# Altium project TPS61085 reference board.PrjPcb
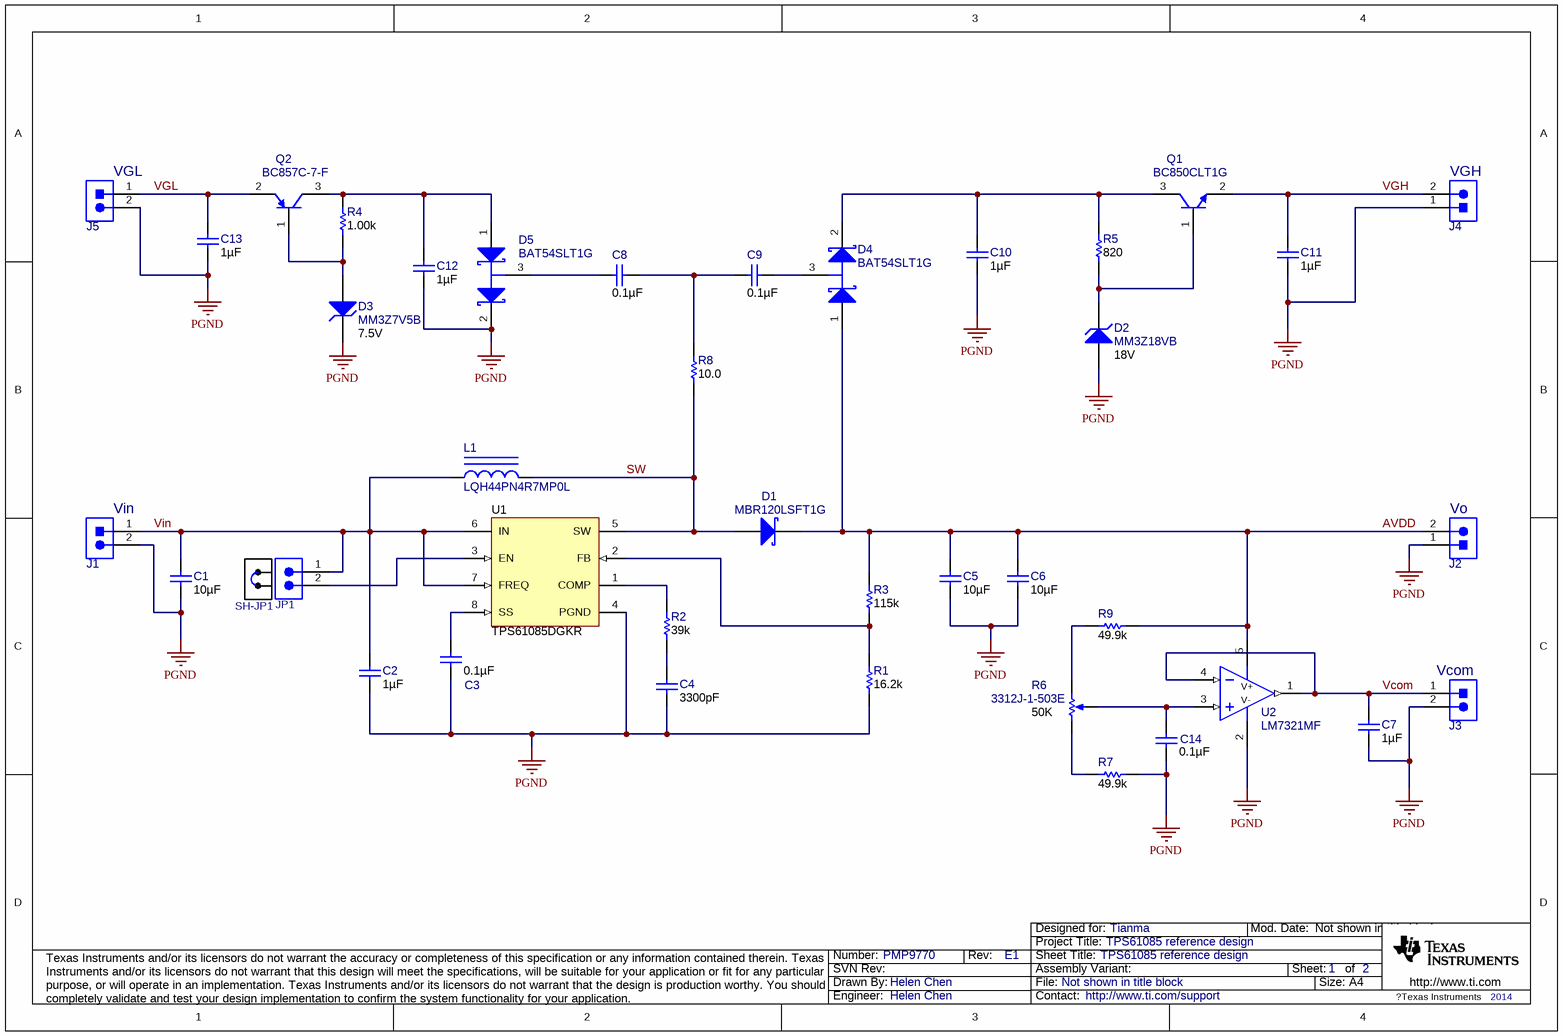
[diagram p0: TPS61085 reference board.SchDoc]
CopyrightYear: 2014; PCB_Layout: Helen Chen; PCB_Rev: E1; PRJ_Customer: Tianma; PRJ_Engineer: Helen Chen; PRJ_Number: PMP9770; PRJ_Title: TPS61085 reference design; SCH_Rev: E1; TechSupport: http://www.ti.com/support; TID: N/A
2 sheets, 51 parts. Net scope: global (net labels, ports and power ports of the same name join across sheets).
Board file: TPS61085 reference board.PcbDoc
Sheets:
  TPS61085 reference board.SchDoc
  TPS61085 reference board_Hardware.SchDoc

## Sheet TPS61085 reference board.SchDoc: TPS61085 reference design
size A4; Date: Not shown in title block; ApprovedBy: Not shown in title block; CheckedBy: Not shown in title block; Author: Not shown in title block; CompanyName: Not shown in title block; DrawnBy: Helen Chen; Engineer: Not shown in title block; Organization: Not shown in title block; Address1: Not shown in title block; Address2: Not shown in title block; Address3: Not shown in title block; Address4: Not shown in title block; DocumentNumber: 1; Revision: Use project parameter SCH_Rev; SheetNumber: 1; SheetTotal: 2; PageSetup: Record=PageOptions¦CenterHorizontal=True¦CenterVertical=True¦PrintScale=0.94¦XCorrection=1.00¦YCorrection=1.00¦PrintKind=0¦BorderSize=5000000¦LeftOffset=0¦BottomOffset=0¦Orientation=2¦PaperLength=1000¦PaperWidth=1000¦Scale=100¦PaperSource=15¦PrintQuality=600¦MediaType=1¦DitherType=10¦PrintScaleMode=1¦PaperKind=Letter

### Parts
C1  ValueDisplayed: 10µF  [0805_HV]  (hidden comment: GRM219R61A106KE44D)
C2  ValueDisplayed: 1µF  [0603]  (hidden comment: GRM185R61C105KE44D)
C3  ValueDisplayed: 0.1µF  [0402]  (hidden comment: GRM155R71C104KA88D)
C4  ValueDisplayed: 3300pF  [0402]  (hidden comment: GRM155R71H332KA01D)
C5  ValueDisplayed: 10µF  [0805_HV]  (hidden comment: C2012X5R1E106K125AB)
C6  ValueDisplayed: 10µF  [0805_HV]  (hidden comment: C2012X5R1E106K125AB)
C7  ValueDisplayed: 1µF  [0603]  (hidden comment: GRM185R61C105KE44D)
C8  ValueDisplayed: 0.1µF  [0603]  (hidden comment: 06035C104KAT2A)
C9  ValueDisplayed: 0.1µF  [0603]  (hidden comment: 06035C104KAT2A)
C10  ValueDisplayed: 1µF  [0603]  (hidden comment: GRM188R61H105KAALD)
C11  ValueDisplayed: 1µF  [0603]  (hidden comment: GRM188R61H105KAALD)
C12  ValueDisplayed: 1µF  [0603]  (hidden comment: GRM185R61C105KE44D)
C13  ValueDisplayed: 1µF  [0603]  (hidden comment: GRM185R61C105KE44D)
C14  ValueDisplayed: 0.1µF  [0402]  (hidden comment: GRM155R71C104KA88D)
D1  MBR120LSFT1G  [SOD-123FL]
D2  MM3Z18VB  value 18V  [SOD-323F]
D3  MM3Z7V5B  value 7.5V  [SOD-323F]
D4  BAT54SLT1G  [SOT-23]
D5  BAT54SLT1G  [SOT-23]
J1  ED555/2DS  [TERM_BLK_ED555-2DS]  (value not drawn)
J2  ED555/2DS  [TERM_BLK_ED555-2DS]  (value not drawn)
J3  ED555/2DS  [TERM_BLK_ED555-2DS]  (value not drawn)
J4  ED555/2DS  [TERM_BLK_ED555-2DS]  (value not drawn)
J5  ED555/2DS  [TERM_BLK_ED555-2DS]  (value not drawn)
JP1  PEC02SAAN  [CONN_PEC02SAAN]  (value not drawn)
L1  LQH44PN4R7MP0L  [IND_LQH44P]
Q1  BC850CLT1G  [SOT-23]
Q2  BC857C-7-F  [SOT-23]
R1  ValueDisplayed: 16.2k  [0402]  (hidden comment: CRCW040216K2FKED)
R2  ValueDisplayed: 39k  [0402]  (hidden comment: CRCW040239K0JNED)
R3  ValueDisplayed: 115k  [0402]  (hidden comment: CRCW0402115KFKED)
R4  ValueDisplayed: 1.00k  [0603]  (hidden comment: RC0603FR-071KL)
R5  ValueDisplayed: 820  [0603]  (hidden comment: RC0603FR-07820RL)
R6  3312J-1-503E  value 50K  [TRIM_3312J]
R7  ValueDisplayed: 49.9k  [0402]  (hidden comment: CRCW040249K9FKED)
R8  ValueDisplayed: 10.0  [0603]  (hidden comment: CRCW060310R0FKEA)
R9  ValueDisplayed: 49.9k  [0402]  (hidden comment: CRCW040249K9FKED)
SH-JP1  969102-0000-DA  [SNT-100-BK-G]  (value not drawn)
U1  TPS61085DGKR  [DGK0008A_N]
U2  LM7321MF  [MF05A_L]

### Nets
PGND: C1.2 C2.2 C3.2 C4.2 C5.2 C6.2 C7.2 C10.2 C11.2 C12.2 C13.2 C14.2 D2.2(A) D3.1(K) D5.2(K) J1.2 J2.1 J3.2 J4.1 J5.2 R1.1 R7.2 U1.4(PGND) U2.2(V-)
AVDD: C5.1 C6.1 D1.1(K) D4.1(A) J2.2 R3.2 R9.2 U2.5(V+)
SW: D1.2(A) L1.2 R8.1 U1.5(SW)
Vcom: C7.1 J3.1 U2.1(OUT) U2.4(IN-)
VGH: C11.1 J4.2 Q1.2(E)
VGL: C13.1 J5.1 Q2.2(E)
Vin: C1.1 C2.1 J1.1 JP1.1 L1.1 U1.6(IN) U1.7(FREQ)
NetC3_1: C3.1 U1.8(SS)
NetC4_1: C4.1 R2.1
NetC8_1: C8.1 C9.2 R8.2
NetC8_2: C8.2 D5.3(C)
NetC9_1: C9.1 D4.3(C)
NetC10_1: C10.1 D4.2(K) Q1.3(C) R5.2
NetC12_1: C12.1 D5.1(A) Q2.3(C) R4.2
NetC14_1: C14.1 R6.2(WIPER) U2.3(IN+)
NetD2_1: D2.1(K) Q1.1(B) R5.1
NetD3_2: D3.2(A) Q2.1(B) R4.1
NetJP1_2: JP1.2 U1.3(EN)
NetR1_2: R1.2 R3.1 U1.2(FB)
NetR2_2: R2.2 U1.1(COMP)
NetR6_1: R6.1(CCW) R7.1
NetR6_3: R6.3(CW) R9.1

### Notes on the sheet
- (near J5) VGL
- (near J4) VGH
- (near J1) Vin
- (near J2) Vo
- (near J3) Vcom

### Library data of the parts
C1 = GRM219R61A106KE44D: CAP, CERM, 10 µF, 10 V, +/- 10%, X5R, 0805; Manufacturer: MuRata; Polarized: N; CompType: Capacitor; Value: 10uF; U/M: EA; Cap_F: 0.00001; Tolerance_%: 10; ESR_ohm: 0.005; Value1: 0.005 ohm; Value2: 10V; TaMin_C: -55; TaMax_C: 85; Cap_Case: 0805
C2 C7 C12 C13 = GRM185R61C105KE44D: CAP, CERM, 1 µF, 16 V, +/- 10%, X5R, 0603; Manufacturer: MuRata; Polarized: N; CompType: Capacitor; Value: 1uF; U/M: EA; Cap_F: 0.000001; Tolerance_%: 10; Value1: Unknown; VDC_V: 16; Value2: 16V; TaMin_C: -55; TaMax_C: 85
C3 C14 = GRM155R71C104KA88D: CAP, CERM, 0.1 µF, 16 V, +/- 10%, X7R, 0402; Manufacturer: MuRata; Polarized: N; CompType: Capacitor; Value: 0.1uF; U/M: EA; Cap_F: 0.0000001; Tolerance_%: 10; Value1: Unknown; VDC_V: 16; Value2: 16V; TaMin_C: -55; TaMax_C: 125
C4 = GRM155R71H332KA01D: CAP, CERM, 3300 pF, 50 V, +/- 10%, X7R, 0402; Manufacturer: MuRata; Polarized: N; CompType: Capacitor; Value: 3300pF; U/M: EA; Cap_F: 0.0000000033; Tolerance_%: 10; Value1: Unknown; VDC_V: 50; Value2: 50V; TaMin_C: -55; TaMax_C: 125
C5 C6 = C2012X5R1E106K125AB: CAP, CERM, 10 µF, 25 V, +/- 10%, X5R, 0805; Manufacturer: TDK; Polarized: N; CompType: Capacitor; Value: 10uF; U/M: EA; Cap_F: 0.00001; Tolerance_%: 10; Value1: Unknown; VDC_V: 25; Value2: 25V; TaMin_C: -55; TaMax_C: 85; Cap_Case: 0805
C8 C9 = 06035C104KAT2A: CAP, CERM, 0.1 µF, 50 V, +/- 10%, X7R, 0603; Manufacturer: AVX; Polarized: N; CompType: Capacitor; Value: 0.1uF; U/M: EA; Cap_F: 0.0000001; Tolerance_%: 10; Value1: Unknown; VDC_V: 50; Value2: 50V; TaMin_C: -55; TaMax_C: 125
C10 C11 = GRM188R61H105KAALD: CAP, CERM, 1 µF, 50 V, +/- 10%, X5R, 0603; Manufacturer: MuRata; Polarized: N; CompType: Capacitor; Value: 1uF; U/M: EA; Cap_F: 0.000001; Tolerance_%: 10; Value1: Unknown; VDC_V: 50; Value2: 50V; TaMin_C: -55; TaMax_C: 85
D1 = MBR120LSFT1G: Diode, Schottky, 20 V, 1 A, SOD-123FL; Manufacturer: ON Semiconductor; U/M: EA; Vf_V: 0.45; Value: 20V; Value1: 1A; Value2: 0.45V; Io_A: 1; Vr_V: 20; TJmax_C: 125; RJC_CperW: 26
D2 = MM3Z18VB: Diode, Zener, 18 V, 200 mW, SOD-323F; Manufacturer: Fairchild Semiconductor; SymbolCreator: a0412235; U/M: EA; Power_W: 0.2; Vz_V: 18; Value1: 0.2W; RJA_CperW: 595
D3 = MM3Z7V5B: Diode, Zener, 7.5 V, 200 mW, SOD-323F; Manufacturer: Fairchild Semiconductor; SymbolCreator: a0412235; U/M: EA; Power_W: 0.2; Vz_V: 7.5; Value1: 0.2W; RJA_CperW: 595
D4 D5 = BAT54SLT1G: Diode, Schottky, 30 V, 0.2 A, SOT-23; Manufacturer: ON Semiconductor; U/M: EA; Vf_V: 0.8; Value: 30V; Value1: 0.2A; Value2: 0.8V; Io_A: 0.2; Vr_V: 30; TJmax_C: 150
J1-J5 = ED555/2DS: Terminal Block, 6A, 3.5mm Pitch, 2-Pos, TH; Manufacturer: On-Shore Technology; SymbolCreator: a0412235; CompType: Connector; U/M: EA
JP1 = PEC02SAAN: Header, 100mil, 2x1, Tin plated, TH; Manufacturer: Sullins Connector Solutions; SymbolCreator: a0412235; U/M: EA
L1 = LQH44PN4R7MP0L: Inductor, Shielded Drum Core, Ferrite, 4.7uH, 1.7A, 0.08 ohm, SMD; Manufacturer: MuRata; ValueDisplayed: 4.7礖; Ind_H: 4.7E-6; Imax_A: 1.7; Irms: 1.7A @ 40C rise; Isat: 1.7A @ 30% inductance drop; DCR_ohm: 0.08; U/M: EA
Q1 = BC850CLT1G, ON Semiconductor: Transistor, NPN, 45 V, 0.1 A, SOT-23; CompType: BJT; PNP: 0; NPN: 1; Vceo_V: 45; Vcesat1_V: 0.7; Value: 45 V; IcRated_A: 0.1; Value1: 0.1 A; HfeMax: 800; TaMin_C: -55; TaMax_C: 150; U/M: EA
Q2 = BC857C-7-F, Diodes Inc.: Transistor, PNP, 45 V, 0.1 A, SOT-23; CompType: BJT; PNP: 1; NPN: 0; Vceo_V: 45; Vcesat1_V: 0.075; Value: 45 V; IcRated_A: 0.1; Value1: 0.1 A; HfeMax: 600; TaMin_C: -65; TaMax_C: 150; U/M: EA
R1 = CRCW040216K2FKED: RES, 16.2 k, 1%, 0.063 W, 0402; Manufacturer: Vishay-Dale; CompType: Resistor; Value: 16.2k; Res_ohm: 16200; Value_Code: 16k2; Tolerance_%: 1; Power_W: 0.063; Value2: 0.063W; VDC_V: 50; TempCo: 100 ppm/C; EIA_Code: E96; U/M: EA
R2 = CRCW040239K0JNED: RES, 39 k, 5%, 0.063 W, 0402; Manufacturer: Vishay-Dale; CompType: Resistor; Value: 39k; Res_ohm: 39000; Value_Code: 39k0; Tolerance_%: 5; Power_W: 0.063; Value2: 0.063W; VDC_V: 50; TempCo: 200 ppm/C; EIA_Code: E24; U/M: EA
R3 = CRCW0402115KFKED: RES, 115 k, 1%, 0.063 W, 0402; Manufacturer: Vishay-Dale; CompType: Resistor; Value: 115k; Res_ohm: 115000; Tolerance_%: 1; Power_W: 0.063; Value2: 0.063W; VDC_V: 50; TempCo: 100 ppm/C; EIA_Code: E96; U/M: EA
R4 = RC0603FR-071KL: RES, 1.00 k, 1%, 0.1 W, 0603; Manufacturer: Yageo America; CompType: Resistor; Value: 1.00k; Res_ohm: 1000; Value_Code: 1k00; Tolerance_%: 1; Power_W: 0.1; Value2: 0.1W; VDC_V: 150; TempCo: 200 ppm/C; EIA_Code: E96; U/M: EA
R5 = RC0603FR-07820RL: RES, 820, 1%, 0.1 W, 0603; Manufacturer: Yageo America; CompType: Resistor; Value: 820; Value_Code: 820R; Tolerance_%: 1; Power_W: 0.1; Value2: 0.1W; VDC_V: 150; TempCo: 200 ppm/C; U/M: EA
R6 = 3312J-1-503E: TRIMMER, 50K Ohm, 0.1 W, SMD; Manufacturer: Bourns; Sim Note: Enter the Resistance value and the set point into parameter fields.; SymbolCreator: a0412235
R7 R9 = CRCW040249K9FKED: RES, 49.9 k, 1%, 0.063 W, 0402; Manufacturer: Vishay-Dale; CompType: Resistor; Value: 49.9k; Res_ohm: 49900; Value_Code: 49k9; Tolerance_%: 1; Power_W: 0.063; Value2: 0.063W; VDC_V: 50; TempCo: 100 ppm/C; EIA_Code: E96; U/M: EA
R8 = CRCW060310R0FKEA: RES, 10.0, 1%, 0.1 W, 0603; Manufacturer: Vishay-Dale; CompType: Resistor; Value: 10.0; Res_ohm: 10; Value_Code: 10R0; Tolerance_%: 1; Power_W: 0.1; Value2: 0.1W; VDC_V: 75; TempCo: 100 ppm/C; EIA_Code: E96; U/M: EA
SH-JP1 = 969102-0000-DA: Shunt, 100mil, Gold plated, Black; Manufacturer: 3M; Alternate Manufacturer: Samtec; Value: 1x2; Note: You can "mate" this to a header by matching the designator.  i.e. use SH-J3 for header J3
U1 = TPS61085DGKR: 18.5 V, 2 A, 650 KHz / 1.2 MHz Step-Up DC-DC Converter with Forced PWM Mode, 2.3 to 6 V, -40 to 85 degC, 8-pin SOP (DGK8), Green (RoHS & no Sb/Br); Manufacturer: Texas Instruments; Alternate Manufacturer: None; Alternate PartNumber: Equivalent; Iout(Max)(A): 2; Iq(Typ)(mA): 0.07; Rating: Catalog; SubFamily: White LED Driver; Switching Frequency(Typ)(kHz): 650, 1200; Topology: Boost; Vin(Max)(V): 6; Vin(Min)(V): 2.3
U2 = LM7321MF: Single 30V High Output Current and Unlimited Capacitive Load Op Amp; Manufacturer: National Semiconductor; Characteristics: LM7321MF Single 30V High Output Current and Unlimited Capacitive Load Op Amp; CompType: OpAmp IC; TaMin_C: -40.0; TaMax_C: 125.0; PowerWise: Y

## Sheet TPS61085 reference board_Hardware.SchDoc: TPS61085 reference design
size 431 x 279 mm; Date: Not shown in title block; ApprovedBy: Not shown in title block; CheckedBy: Not shown in title block; Author: Not shown in title block; CompanyName: Not shown in title block; DrawnBy: Helen Chen; Engineer: Not shown in title block; Organization: Not shown in title block; Address1: Not shown in title block; Address2: Not shown in title block; Address3: Not shown in title block; Address4: Not shown in title block; DocumentNumber: 1; Revision: Use project parameter SCH_Rev; SheetNumber: 2; SheetTotal: 2; PageSetup: Record=PageOptions¦CenterHorizontal=True¦CenterVertical=True¦PrintScale=1.00¦XCorrection=1.00¦YCorrection=1.00¦PrintKind=0¦BorderSize=5000000¦LeftOffset=0¦BottomOffset=0¦Orientation=2¦PaperLength=1000¦PaperWidth=1000¦Scale=100¦PaperSource=15¦PrintQuality=600¦MediaType=1¦DitherType=10¦PaperKind=Letter¦PrintScaleMode=1
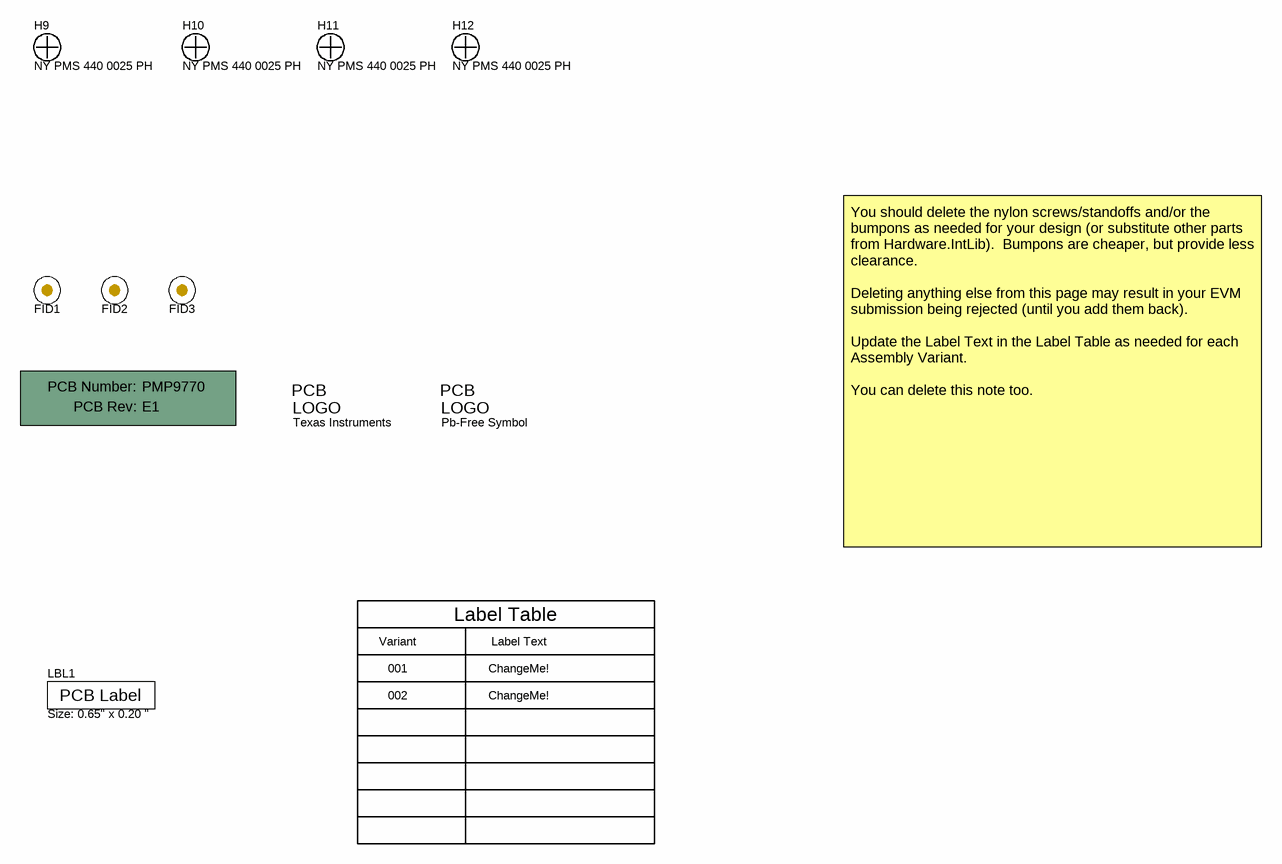
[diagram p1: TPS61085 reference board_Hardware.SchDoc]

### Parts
!PCB1  Printed Circuit Board  (value not drawn)  (mechanical)
FID1  Fiducial  [Fiducial10-20]  (value not drawn)
FID2  Fiducial  [Fiducial10-20]  (value not drawn)
FID3  Fiducial  [Fiducial10-20]  (value not drawn)
H9  NY PMS 440 0025 PH  [NY PMS 440 0025 PH]
H10  NY PMS 440 0025 PH  [NY PMS 440 0025 PH]
H11  NY PMS 440 0025 PH  [NY PMS 440 0025 PH]
H12  NY PMS 440 0025 PH  [NY PMS 440 0025 PH]
LBL1  Size: 0.65" x 0.20 "  [Label_650x200]
Logo1  Texas Instruments  [TI_Stacked_SolderMask_Small]  (no BOM)
Logo2  Pb-Free Symbol  [Pb-Free_Overlay_Small]  (no BOM)

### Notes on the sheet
- You should delete the nylon screws/standoffs and/or the bumpons as needed for your design (or substitute other parts from Hardware.IntLib).  Bumpons are cheaper, but provide less clearance.
  Deleting anything else from this page may result in your EVM submission being rejected (until you add them back).
  Update the Label Text in the Label Table as needed for each Assembly Variant.
  You can delete this note too.
- Variant
- Label Table
- Label Text
- 001
- 002
- ChangeMe!

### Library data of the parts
!PCB1 = PCB: Manufacturer: Any; PartNumber: PMP9770; SymbolCreator: a0412235
FID1-FID3 = Fiducial: Fiducial mark.  There is nothing to buy or mount.; SymbolCreator: codlsc
H9-H12 = NY PMS 440 0025 PH: Machine Screw, Round, #4-40 x 1/4, Nylon, Philips panhead; Manufacturer: B&F Fastener Supply; CompType: Hardware; SymbolCreator: codlsc; U/M: EA
LBL1 = THT-14-423-10: Thermal Transfer Printable Labels, 0.650" W x 0.200" H - 10,000 per roll; Manufacturer: Brady; SymbolCreator: a0412235; CompType: Label
Logo1 = TI_Logo: Texas Instrument Corporate Signature; SymbolCreator: codlsc
Logo2 = Pb-Free: SymbolCreator: a0412235

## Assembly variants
001: not fitted FID1 FID2 FID3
